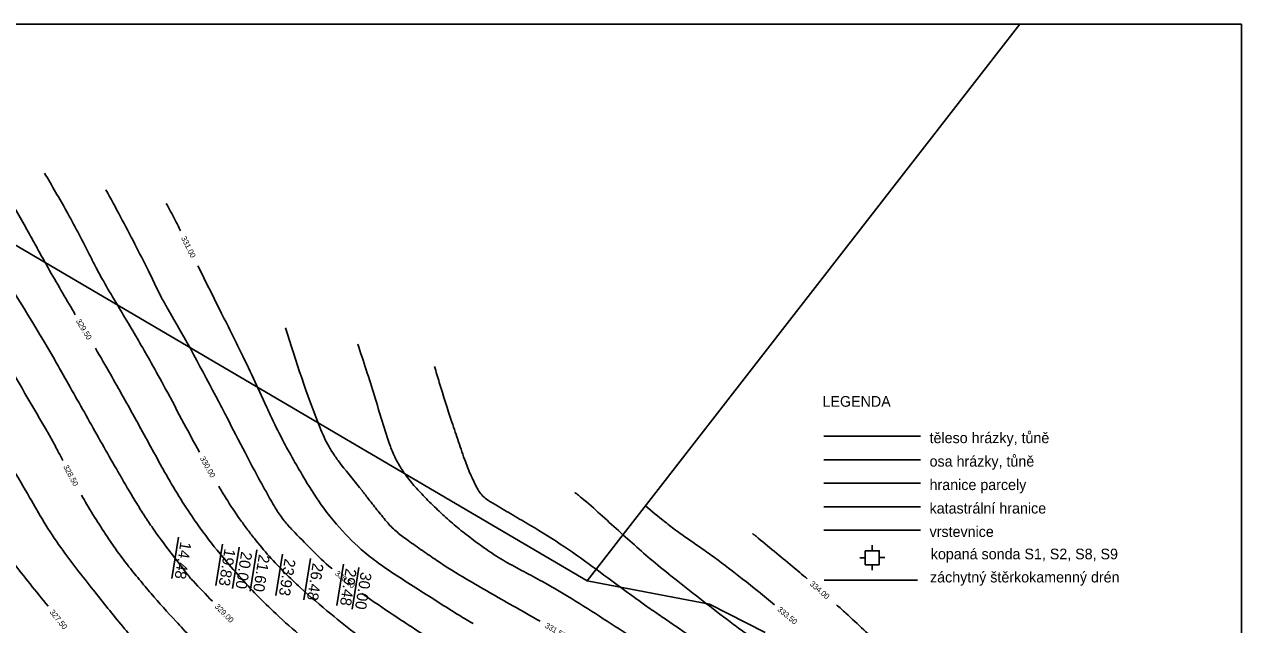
# Model space of a CAD drawing. Extents: x -564037 to -563827, y -1163561 to -1163412.
# Drawn here: x -563935.6 to -563826.5, y -1163466.2 to -1163412.5 of the extents above; entities that cross this region are included whole.
import ezdxf

# ---------------------------------------------------------------- set-up
doc = ezdxf.new("R2010")
doc.units = 0
for name, color, linetype in [('_popis staničení T2', 7, 'Continuous'), ('_rám PH2 a PH4', 7, 'Continuous'), ('Hranice parcel', 7, 'Continuous'), ('Obvod PU', 7, 'Continuous'), ('Vrstva 24', 7, 'Continuous'), ('Vrstva 25', 7, 'Continuous'), ('Vrstva 26', 7, 'Continuous')]:
    doc.layers.add(name, color=color, linetype=linetype)

msp = doc.modelspace()

# ---------------------------------------------------------------- linework, layer by layer
at = {"layer": '_popis staničení T2'}
for p, q in [((-563922.38, -1163462.12), (-563921.78, -1163458.41)), ((-563918.43, -1163462.74), (-563917.83, -1163459.04)), ((-563916.93, -1163463), (-563916.33, -1163459.3)), ((-563915.36, -1163463.25), (-563914.76, -1163459.55)), ((-563913.05, -1163463.63), (-563912.45, -1163459.92)), ((-563910.54, -1163464.03), (-563909.94, -1163460.33)), ((-563907.58, -1163464.51), (-563906.98, -1163460.81)), ((-563906.22, -1163464.84), (-563905.62, -1163461.13))]:
    msp.add_line(p, q, dxfattribs=at)
at = {"layer": '_rám PH2 a PH4'}
for p, q in [((-563826.51, -1163412.49), (-564036.51, -1163412.49)), ((-563826.51, -1163560.99), (-563826.51, -1163412.49)), ((-563863.94, -1163449.37), (-563855.28, -1163449.37)), ((-563863.94, -1163451.47), (-563855.28, -1163451.47)), ((-563863.94, -1163453.57), (-563855.28, -1163453.57)), ((-563863.94, -1163455.68), (-563855.28, -1163455.68)), ((-563863.94, -1163457.78), (-563855.28, -1163457.78)), ((-563859.61, -1163459.62), (-563859.61, -1163459.12)), ((-563860.23, -1163460.27), (-563860.73, -1163460.27)), ((-563858.98, -1163460.24), (-563858.48, -1163460.24)), ((-563859.62, -1163460.87), (-563859.62, -1163461.37)), ((-563863.91, -1163462.26), (-563855.54, -1163462.26))]:
    msp.add_line(p, q, dxfattribs=at)
msp.add_lwpolyline([(-563860.23, -1163459.62), (-563858.98, -1163459.62), (-563858.98, -1163460.87), (-563860.23, -1163460.87)], close=True, dxfattribs=at)
at = {"layer": 'Hranice parcel'}
msp.add_lwpolyline([(-563885.14, -1163462.32), (-563943.67, -1163427.99), (-563964.47, -1163416.08)], dxfattribs=at)
at = {"layer": 'Obvod PU'}
for points in [[(-563846.38, -1163412.49), (-563885.14, -1163462.32)], [(-563885.14, -1163462.32), (-563874.2, -1163464.42), (-563869.21, -1163466.93)]]:
    msp.add_lwpolyline(points, dxfattribs=at)
at = {"layer": 'Vrstva 24'}
for points in [[(-563921.58, -1163430.99), (-563922.1, -1163429.96), (-563922.86, -1163428.53)], [(-563918.73, -1163464.14), (-563920.47, -1163462.33), (-563920.75, -1163462.02), (-563920.93, -1163461.79), (-563924.08, -1163457.59), (-563924.81, -1163456.5), (-563925.51, -1163455.39), (-563926.86, -1163453.13), (-563927.09, -1163452.73), (-563927.34, -1163452.3), (-563929.89, -1163447.79), (-563932.42, -1163443.31), (-563932.86, -1163442.53), (-563938.36, -1163433.35), (-563938.44, -1163433.21), (-563940.92, -1163429.19)], [(-563895.38, -1163466.15), (-563896.62, -1163465.4), (-563900.27, -1163463.09), (-563904.04, -1163460.59), (-563905.39, -1163459.51), (-563907.61, -1163457.24), (-563908.76, -1163455.82), (-563910.43, -1163453.26), (-563912.44, -1163449.7), (-563913.55, -1163447.46), (-563914.15, -1163446.16), (-563914.75, -1163444.86), (-563915.97, -1163442.27), (-563917.91, -1163438.37), (-563920.03, -1163434.12)], [(-563919.38, -1163476.01), (-563920.12, -1163475.14), (-563923.22, -1163471.06), (-563923.7, -1163470.36), (-563924.16, -1163469.69), (-563926.77, -1163466.4), (-563928.09, -1163464.78), (-563929.4, -1163463.14), (-563932.31, -1163459.34), (-563933.83, -1163457.04), (-563935.11, -1163454.85), (-563938.34, -1163449.38), (-563939.75, -1163446.92), (-563941.15, -1163444.46), (-563942.64, -1163441.76)], [(-563881.22, -1163467.31), (-563886.92, -1163463.69), (-563888.12, -1163462.97), (-563888.75, -1163462.61), (-563889.58, -1163462.16), (-563890.42, -1163461.71), (-563891.25, -1163461.27), (-563892.09, -1163460.81), (-563893.67, -1163459.85), (-563894.43, -1163459.32), (-563895.18, -1163458.78), (-563896.46, -1163457.8), (-563897.67, -1163456.77), (-563898.84, -1163455.68), (-563899.98, -1163454.54), (-563900.9, -1163453.5), (-563901.73, -1163452.38), (-563902.04, -1163451.88), (-563902.33, -1163451.36), (-563902.78, -1163450.28), (-563904.21, -1163445.76), (-563905.71, -1163441.12)], [(-563862.95, -1163472.88), (-563865.36, -1163470.94), (-563867.28, -1163469.56), (-563868.39, -1163468.78), (-563869.51, -1163468), (-563870.63, -1163467.22), (-563871.74, -1163466.44), (-563872.34, -1163465.99), (-563877.17, -1163462.24), (-563879.04, -1163460.73), (-563880.71, -1163459.29), (-563882.35, -1163457.82), (-563883.98, -1163456.34), (-563885.65, -1163454.89), (-563886.03, -1163454.58), (-563886.15, -1163454.49), (-563886.22, -1163454.45), (-563886.25, -1163454.42), (-563886.27, -1163454.41)], [(-563865.43, -1163462.14), (-563866.77, -1163461.01), (-563870.02, -1163458.33), (-563870.14, -1163458.23), (-563870.19, -1163458.19), (-563870.34, -1163458.09)], [(-563941.26, -1163493.01), (-563939, -1163490.7), (-563935.17, -1163486.58), (-563933.6, -1163484.77), (-563933.04, -1163483.79), (-563932.45, -1163481.94), (-563932.39, -1163481.58), (-563932.34, -1163479.09), (-563932.36, -1163478.88), (-563932.37, -1163478.7), (-563932.36, -1163477.98), (-563932.29, -1163477.27), (-563932.23, -1163476.55), (-563932.24, -1163475.83), (-563932.27, -1163475.75), (-563932.33, -1163475.65), (-563935.19, -1163471.03), (-563938.35, -1163465.93), (-563938.45, -1163465.79), (-563938.86, -1163465.28), (-563944.23, -1163458.58)], [(-563834.56, -1163494.64), (-563836.37, -1163491.68), (-563837.26, -1163490.4), (-563838.09, -1163489.32), (-563838.93, -1163488.26), (-563840.68, -1163486.18), (-563843.6, -1163482.93), (-563845.38, -1163480.99), (-563847.69, -1163478.52), (-563848.87, -1163477.31), (-563850.08, -1163476.13), (-563853.18, -1163473.26), (-563856.32, -1163470.43), (-563856.74, -1163470.06), (-563856.9, -1163469.93), (-563857.18, -1163469.67), (-563858.78, -1163468.19), (-563860.37, -1163466.7), (-563861.97, -1163465.22), (-563862.81, -1163464.45)]]:
    msp.add_spline(points, degree=3, dxfattribs=at)
at = {"layer": 'Vrstva 25'}
for points in [[(-563919.9, -1163450.79), (-563921.28, -1163448.23), (-563922.95, -1163445.09), (-563924.22, -1163442.79), (-563926.26, -1163439.27), (-563928.5, -1163435.47), (-563929.15, -1163434.28), (-563929.83, -1163432.95), (-563931.81, -1163429.21), (-563933.77, -1163425.82)], [(-563887.06, -1163480.68), (-563889.48, -1163478.12), (-563890.68, -1163477.11), (-563891.26, -1163476.71), (-563892.36, -1163476), (-563898.34, -1163472.15), (-563901.29, -1163470.25), (-563905.74, -1163467.17), (-563908.13, -1163465.28), (-563910.84, -1163462.93), (-563912.22, -1163461.62), (-563914.97, -1163458.53), (-563915.64, -1163457.66), (-563916.29, -1163456.77), (-563917.51, -1163454.93), (-563918.17, -1163453.84)]]:
    msp.add_spline(points, degree=3, dxfattribs=at)
at = {"layer": 'Vrstva 26'}
for points in [[(-563932.12, -1163451.55), (-563932.51, -1163450.83), (-563933.08, -1163449.75), (-563933.69, -1163448.68), (-563937.9, -1163441.49), (-563939.67, -1163438.54), (-563943.81, -1163431.76), (-563944.65, -1163430.42), (-563945.42, -1163429.3), (-563947.84, -1163425.66), (-563950.04, -1163421.85), (-563951.29, -1163419.54), (-563951.84, -1163418.69), (-563952.5, -1163417.84), (-563953.82, -1163416.23)], [(-563931.02, -1163438.49), (-563931.13, -1163438.3), (-563933.46, -1163434.28), (-563933.88, -1163433.53), (-563934.3, -1163432.77), (-563934.71, -1163432.02), (-563935.13, -1163431.27), (-563937.07, -1163427.91), (-563938.14, -1163426.22), (-563939.3, -1163424.52)], [(-563908.01, -1163461.23), (-563908.06, -1163461.19), (-563909.84, -1163459.52), (-563911.55, -1163457.78), (-563912.31, -1163456.93), (-563913, -1163455.94), (-563913.8, -1163454.56), (-563915.81, -1163450.84), (-563917.45, -1163447.66), (-563918.16, -1163446.3), (-563922.78, -1163437.87), (-563923.03, -1163437.44), (-563923.28, -1163436.98), (-563923.88, -1163435.77), (-563924.47, -1163434.56), (-563925.68, -1163432.16), (-563928.28, -1163427.3)], [(-563933.46, -1163464.59), (-563936.66, -1163460.58), (-563938.76, -1163457.78), (-563942.84, -1163451.43), (-563944.76, -1163447.97), (-563948.45, -1163440.73), (-563949, -1163439.65), (-563949.55, -1163438.67), (-563950.17, -1163437.66), (-563950.81, -1163436.67), (-563951.44, -1163435.67), (-563952.06, -1163434.65), (-563954.29, -1163430.74), (-563955.08, -1163429.28)], [(-563889.36, -1163465.94), (-563891.82, -1163464.54), (-563895.95, -1163462.17), (-563898.61, -1163460.5), (-563899.91, -1163459.61), (-563901.2, -1163458.7), (-563902.16, -1163457.97), (-563902.61, -1163457.57), (-563903.02, -1163457.13), (-563903.88, -1163456.08), (-563904.72, -1163455.02), (-563905.32, -1163454.24), (-563907.18, -1163451.93), (-563907.75, -1163451.15), (-563908.02, -1163450.74), (-563908.28, -1163450.32), (-563909.1, -1163448.57), (-563912.19, -1163439.67)], [(-563903.21, -1163473.11), (-563903.34, -1163473.04), (-563904.67, -1163472.17), (-563906.5, -1163470.85), (-563910.71, -1163467.34), (-563913.03, -1163465.28), (-563914.75, -1163463.59), (-563917.78, -1163460.23), (-563919.82, -1163457.6), (-563921.06, -1163455.8), (-563922.39, -1163453.66), (-563923.26, -1163452.13), (-563925.57, -1163447.92), (-563926.72, -1163445.85), (-563927.87, -1163443.82), (-563929.22, -1163441.49)], [(-563871.86, -1163470.11), (-563873.03, -1163469.28), (-563875.16, -1163467.79), (-563876.36, -1163466.96), (-563877.56, -1163466.14), (-563878.77, -1163465.32), (-563879.97, -1163464.48), (-563881.54, -1163463.35), (-563887.19, -1163459.27), (-563890.24, -1163457.35), (-563891.79, -1163456.44), (-563893.34, -1163455.52), (-563894.17, -1163455), (-563894.59, -1163454.63), (-563894.92, -1163454.18), (-563895.24, -1163453.56), (-563895.54, -1163452.93), (-563896.06, -1163451.64), (-563896.67, -1163449.88), (-563897.27, -1163448.11), (-563898.4, -1163444.56), (-563898.83, -1163443.13)], [(-563905.62, -1163487.17), (-563905.71, -1163486.43), (-563906.14, -1163484.4), (-563906.33, -1163483.59), (-563906.62, -1163482.77), (-563906.83, -1163482.38), (-563907.08, -1163482.01), (-563907.56, -1163481.45), (-563908.07, -1163480.92), (-563908.73, -1163480.27), (-563912.1, -1163476.61), (-563915.34, -1163473.08), (-563915.91, -1163472.42), (-563916.76, -1163471.47), (-563918.06, -1163470.07), (-563919.38, -1163468.7), (-563920.7, -1163467.33), (-563922, -1163465.94), (-563924.22, -1163463.46), (-563925.29, -1163462.19), (-563926.34, -1163460.89), (-563927.35, -1163459.54), (-563928.17, -1163458.34), (-563930.36, -1163454.82), (-563930.46, -1163454.64)], [(-563868.37, -1163464.45), (-563871.25, -1163462.13), (-563873.73, -1163460.24), (-563874.85, -1163459.44), (-563875.98, -1163458.66), (-563877.1, -1163457.87), (-563878.19, -1163457.03), (-563879.96, -1163455.58)], [(-563873.45, -1163489.45), (-563873.73, -1163488.98), (-563874.78, -1163487.44), (-563876.78, -1163484.89), (-563881.14, -1163480.24), (-563883.66, -1163478.01), (-563887.51, -1163475.07), (-563890.54, -1163473.02), (-563896.23, -1163469.44), (-563897.37, -1163468.71), (-563897.94, -1163468.34), (-563899.48, -1163467.35), (-563904.89, -1163463.75), (-563905.31, -1163463.45)]]:
    msp.add_spline(points, degree=3, dxfattribs=at)

# ---------------------------------------------------------------- texts
at = {"layer": '_popis staničení T2'}
for s, p in [('14.48', (-563921.59, -1163458.77)), ('19.83', (-563917.64, -1163459.39)), ('20.00', (-563916.14, -1163459.65)), ('21.60', (-563914.56, -1163459.91)), ('23.93', (-563912.25, -1163460.28)), ('26.48', (-563909.74, -1163460.68)), ('29.48', (-563906.78, -1163461.16)), ('30.00', (-563905.43, -1163461.49))]:
    msp.add_text(s, height=1, rotation=260.811, dxfattribs=at).set_placement(p)
at = {"layer": '_rám PH2 a PH4'}
for s, p in [('LEGENDA', (-563864.06, -1163446.73)), ('těleso hrázky, tůně', (-563854.47, -1163449.99)), ('osa hrázky, tůně', (-563854.47, -1163452.09)), ('hranice parcely', (-563854.47, -1163454.19)), ('katastrální hranice', (-563854.47, -1163456.29)), ('vrstevnice', (-563854.47, -1163458.39)), ('kopaná sonda S1, S2, S8, S9', (-563854.36, -1163460.39)), ('záchytný štěrkokamenný drén', (-563854.43, -1163462.46))]:
    msp.add_text(s, height=0.956, rotation=360, dxfattribs=at).set_placement(p)
at = {"layer": 'Vrstva 25'}
for s, rotation, p in [('331.00', 296.3844, (-563921.55, -1163431.62)), ('329.50', 300.895, (-563930.98, -1163439.04)), ('330.00', 299.4755, (-563919.87, -1163451.35)), ('328.50', 298.2595, (-563932.11, -1163452.1)), ('330.50', 320.8421, (-563907.79, -1163461.74)), ('334.00', 318.7306, (-563865.24, -1163462.66)), ('329.00', 314.6992, (-563918.56, -1163464.66)), ('333.50', 320.2433, (-563868.15, -1163464.96)), ('327.50', 308.6467, (-563933.35, -1163465.13)), ('331.50', 329.5681, (-563888.98, -1163466.46))]:
    msp.add_text(s, height=0.5, rotation=rotation, dxfattribs=at).set_placement(p)

doc.saveas('drawing.dxf')
